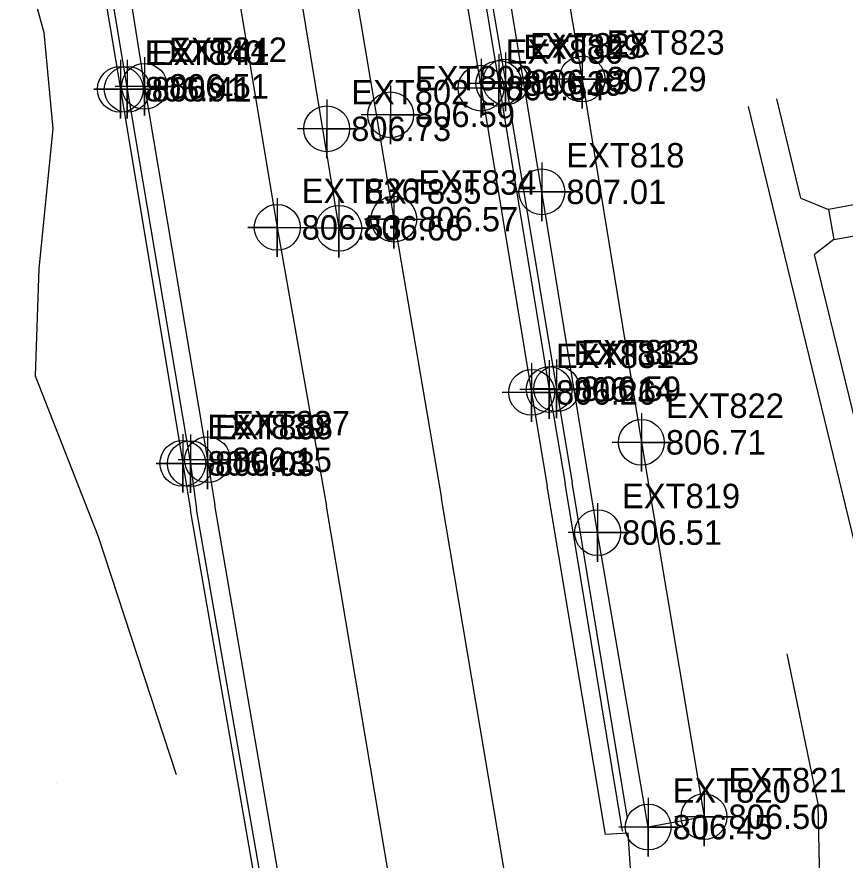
# Model space of a CAD drawing. Extents: x 1762120 to 1766775, y 709485 to 712965.
# Drawn here: x 1763815.9 to 1763900.7, y 712472.4 to 712558.7 of the extents above; entities that cross this region are included whole.
import ezdxf

# ---------------------------------------------------------------- set-up
doc = ezdxf.new("R2010")
doc.units = 0
for name, color, linetype in [('Exist DTM Crownline', 7, 'Continuous'), ('Exist DTM Crownline Cogo Elevation', 7, 'Continuous'), ('Exist DTM Crownline Cogo Number', 7, 'Continuous'), ('Exist DTM Crownline Cogo Point CELL', 7, 'Continuous'), ('Exist DTM Drainline', 7, 'Continuous'), ('Exist DTM Drainline Cogo Elevation', 7, 'Continuous'), ('Exist DTM Drainline Cogo Number', 7, 'Continuous'), ('Exist DTM Drainline Cogo Point CELL', 7, 'Continuous'), ('Exist DTM QL2 LIDAR Elevation Point', 7, 'Continuous'), ('Exist Roads Curbs', 7, 'Continuous'), ('Exist Roads Curbs Cogo Elevation', 7, 'Continuous'), ('Exist Roads Curbs Cogo Number', 7, 'Continuous'), ('Exist Roads Curbs Cogo Point CELL', 7, 'Continuous'), ('Exist Roads EOP', 7, 'Continuous'), ('Exist Roads EOP Cogo Elevation', 7, 'Continuous'), ('Exist Roads EOP Cogo Number', 7, 'Continuous'), ('Exist Roads EOP Cogo Point CELL', 7, 'Continuous'), ('Exist Roads EOP Other', 7, 'Continuous'), ('Exist Roads EOP Other Cogo Elevation', 7, 'Continuous'), ('Exist Roads EOP Other Cogo Number', 7, 'Continuous'), ('Exist Roads EOP Other Cogo Point CELL', 7, 'Continuous'), ('Exist Roads EOT', 7, 'Continuous'), ('Exist Roads EOT Cogo Elevation', 7, 'Continuous'), ('Exist Roads EOT Cogo Number', 7, 'Continuous'), ('Exist Roads EOT Cogo Point CELL', 7, 'Continuous'), ('Exist Utilities Sanitary Sewer UG Line Cogo Elevation', 7, 'Continuous'), ('Exist Utilities Sanitary Sewer UG Line Cogo Number', 7, 'Continuous'), ('Exist Utilities Sanitary Sewer UG Line Cogo Point CELL', 7, 'Continuous'), ('Exist Utilities Water UG Line SUE LOS C Cogo Elevation', 7, 'Continuous'), ('Exist Utilities Water UG Line SUE LOS C Cogo Number', 7, 'Continuous'), ('Exist Utilities Water UG Line SUE LOS C Cogo Point CELL', 7, 'Continuous'), ('PH Exist DTM Breakline', 7, 'Continuous')]:
    doc.layers.add(name, color=color, linetype=linetype)

msp = doc.modelspace()

# ---------------------------------------------------------------- linework, layer by layer
at = {"layer": 'Exist DTM Crownline'}
msp.add_line((1763843.626, 712568.925), (1763848.874, 712537.033), dxfattribs=at)
at = {"layer": 'Exist DTM Crownline Cogo Point CELL'}
msp.add_lwpolyline([(1763848.874, 712540.033), (1763848.874, 712534.033), (1763848.874, 712537.033), (1763851.874, 712537.033), (1763845.874, 712537.033)], dxfattribs=at)
msp.add_circle((1763848.874, 712537.033), 2.344, dxfattribs=at)
at = {"layer": 'Exist DTM Drainline'}
for p, q in [((1763877.892, 712475.314), (1763872.037, 712510.908)), ((1763841.037, 712469.687), (1763834.31, 712508.288))]:
    msp.add_line(p, q, dxfattribs=at)
for points in [[(1763824.048, 712570.37), (1763827.225, 712551.256), (1763833.688, 712512.933), (1763834.31, 712508.288)], [(1763862.254, 712569.784), (1763865.235, 712551.849), (1763870.388, 712520.524), (1763872.037, 712510.908)]]:
    msp.add_lwpolyline(points, dxfattribs=at)
at = {"layer": 'Exist DTM Drainline Cogo Point CELL'}
for points in [[(1763827.225, 712554.256), (1763827.225, 712548.256), (1763827.225, 712551.256), (1763830.225, 712551.256), (1763824.225, 712551.256)], [(1763865.235, 712554.849), (1763865.235, 712548.849), (1763865.235, 712551.849), (1763868.235, 712551.849), (1763862.235, 712551.849)], [(1763870.388, 712523.524), (1763870.388, 712517.524), (1763870.388, 712520.524), (1763873.388, 712520.524), (1763867.388, 712520.524)], [(1763833.688, 712515.933), (1763833.688, 712509.933), (1763833.688, 712512.933), (1763836.688, 712512.933), (1763830.688, 712512.933)]]:
    msp.add_lwpolyline(points, dxfattribs=at)
for centre in [(1763865.235, 712551.849), (1763827.225, 712551.256), (1763870.388, 712520.524), (1763833.688, 712512.933)]:
    msp.add_circle(centre, 2.344, dxfattribs=at)
at = {"layer": 'Exist DTM QL2 LIDAR Elevation Point'}
for p, q in [((1763900, 712550), (1763900, 712550)), ((1763819.96, 712480.153), (1763819.96, 712480.153))]:
    msp.add_line(p, q, dxfattribs=at)
at = {"layer": 'Exist Roads Curbs'}
for p, q in [((1763878.401, 712476.66), (1763872.734, 712511.007)), ((1763840.219, 712470.768), (1763833.683, 712508.175))]:
    msp.add_line(p, q, dxfattribs=at)
for points in [[(1763823.372, 712570.121), (1763826.523, 712551.26), (1763832.916, 712512.967), (1763833.683, 712508.175)], [(1763862.851, 712570.097), (1763865.927, 712552.006), (1763871.153, 712520.608), (1763872.734, 712511.007)]]:
    msp.add_lwpolyline(points, dxfattribs=at)
at = {"layer": 'Exist Roads Curbs Cogo Point CELL'}
for points in [[(1763865.927, 712555.006), (1763865.927, 712549.006), (1763865.927, 712552.006), (1763863.197, 712552.006), (1763868.927, 712552.006)], [(1763826.523, 712554.26), (1763826.523, 712548.26), (1763826.523, 712551.26), (1763823.793, 712551.26), (1763829.523, 712551.26)], [(1763871.153, 712523.608), (1763871.153, 712517.608), (1763871.153, 712520.608), (1763868.423, 712520.608), (1763874.153, 712520.608)], [(1763832.916, 712515.967), (1763832.916, 712509.967), (1763832.916, 712512.967), (1763830.186, 712512.967), (1763835.916, 712512.967)]]:
    msp.add_lwpolyline(points, dxfattribs=at)
for centre in [(1763865.927, 712552.006), (1763826.523, 712551.26), (1763871.153, 712520.608), (1763832.916, 712512.967)]:
    msp.add_circle(centre, 2.344, dxfattribs=at)
at = {"layer": 'Exist Roads EOP'}
for points in [[(1763825.965, 712570.729), (1763828.989, 712551.557), (1763835.435, 712513.335), (1763836.189, 712508.687)], [(1763860.431, 712569.332), (1763863.418, 712551.371), (1763868.592, 712520.228), (1763870.179, 712510.62)], [(1763884.183, 712443.669), (1763879.61, 712457.472), (1763878.458, 712475.13), (1763876.164, 712474.961), (1763870.179, 712510.62)], [(1763839.345, 712446.056), (1763842.4, 712453.309), (1763841.183, 712469.399), (1763842.828, 712470.046), (1763836.189, 712508.687)]]:
    msp.add_lwpolyline(points, dxfattribs=at)
at = {"layer": 'Exist Roads EOP Cogo Point CELL'}
for points in [[(1763828.989, 712554.557), (1763828.989, 712548.557), (1763828.989, 712551.557), (1763831.989, 712551.557), (1763825.989, 712551.557)], [(1763863.418, 712554.371), (1763863.418, 712548.371), (1763863.418, 712551.371), (1763866.418, 712551.371), (1763860.418, 712551.371)], [(1763868.592, 712523.228), (1763868.592, 712517.228), (1763868.592, 712520.228), (1763871.592, 712520.228), (1763865.592, 712520.228)], [(1763835.435, 712516.335), (1763835.435, 712510.335), (1763835.435, 712513.335), (1763838.435, 712513.335), (1763832.435, 712513.335)]]:
    msp.add_lwpolyline(points, dxfattribs=at)
for centre in [(1763828.989, 712551.557), (1763863.418, 712551.371), (1763868.592, 712520.228), (1763835.435, 712513.335)]:
    msp.add_circle(centre, 2.344, dxfattribs=at)
at = {"layer": 'Exist Roads EOP Other'}
msp.add_lwpolyline([(1763854.132, 712635.686), (1763859.673, 712642.69), (1763861.796, 712624.763), (1763862.778, 712618.431), (1763867.533, 712589.151), (1763873.757, 712552.303), (1763879.823, 712515.119), (1763886.226, 712476.795), (1763880.517, 712475.736), (1763875.337, 712505.878), (1763869.64, 712540.755), (1763863.568, 712577.565), (1763858.925, 712604.892)], close=True, dxfattribs=at)
at = {"layer": 'Exist Roads EOP Other Cogo Point CELL'}
for points in [[(1763873.757, 712555.303), (1763873.757, 712549.303), (1763873.757, 712552.303), (1763876.757, 712552.303), (1763870.757, 712552.303)], [(1763869.64, 712543.755), (1763869.64, 712537.755), (1763869.64, 712540.755), (1763872.64, 712540.755), (1763866.64, 712540.755)], [(1763879.823, 712518.119), (1763879.823, 712512.119), (1763879.823, 712515.119), (1763882.823, 712515.119), (1763876.823, 712515.119)], [(1763875.337, 712508.878), (1763875.337, 712502.878), (1763875.337, 712505.878), (1763878.337, 712505.878), (1763872.337, 712505.878)], [(1763886.226, 712479.795), (1763886.226, 712473.795), (1763886.226, 712476.795), (1763889.226, 712476.795), (1763883.226, 712476.795)], [(1763880.517, 712478.736), (1763880.517, 712472.736), (1763880.517, 712475.736), (1763883.517, 712475.736), (1763877.517, 712475.736)]]:
    msp.add_lwpolyline(points, dxfattribs=at)
for centre in [(1763873.757, 712552.303), (1763869.64, 712540.755), (1763879.823, 712515.119), (1763875.337, 712505.878), (1763886.226, 712476.795), (1763880.517, 712475.736)]:
    msp.add_circle(centre, 2.344, dxfattribs=at)
at = {"layer": 'Exist Roads EOT'}
for points in [[(1763849.139, 712569.759), (1763854.496, 712537.963), (1763859.372, 712509.363)], [(1763837.441, 712567.81), (1763842.568, 712537.12), (1763847.598, 712508.586)], [(1763870.661, 712442.063), (1763865.561, 712472.808), (1763859.372, 712509.363)], [(1763858.644, 712443.141), (1763854.01, 712470.555), (1763847.598, 712508.586)]]:
    msp.add_lwpolyline(points, dxfattribs=at)
at = {"layer": 'Exist Roads EOT Cogo Point CELL'}
for points in [[(1763854.496, 712540.963), (1763854.496, 712534.963), (1763854.496, 712537.963), (1763851.496, 712537.963), (1763857.496, 712537.963)], [(1763842.568, 712540.12), (1763842.568, 712534.12), (1763842.568, 712537.12), (1763839.568, 712537.12), (1763845.568, 712537.12)]]:
    msp.add_lwpolyline(points, dxfattribs=at)
for centre in [(1763854.496, 712537.963), (1763842.568, 712537.12)]:
    msp.add_circle(centre, 2.344, dxfattribs=at)
at = {"layer": 'Exist Utilities Sanitary Sewer UG Line Cogo Point CELL'}
msp.add_lwpolyline([(1763854.167, 712551.643), (1763854.167, 712545.643), (1763854.167, 712548.643), (1763857.167, 712548.643), (1763851.167, 712548.643)], dxfattribs=at)
msp.add_circle((1763854.167, 712548.643), 2.344, dxfattribs=at)
at = {"layer": 'Exist Utilities Water UG Line SUE LOS C Cogo Point CELL'}
msp.add_lwpolyline([(1763847.633, 712550.215), (1763847.633, 712544.215), (1763847.633, 712547.215), (1763850.633, 712547.215), (1763844.633, 712547.215)], dxfattribs=at)
msp.add_circle((1763847.633, 712547.215), 2.344, dxfattribs=at)
at = {"layer": 'PH Exist DTM Breakline'}
for p, q in [((1763896.143, 712540.128), (1763893.68, 712550.269)), ((1763902.567, 712500.966), (1763890.781, 712549.497)), ((1763896.143, 712540.128), (1763898.962, 712538.961)), ((1763899.523, 712535.884), (1763897.544, 712534.36)), ((1763903.063, 712511.632), (1763897.544, 712534.36))]:
    msp.add_line(p, q, dxfattribs=at)
for points in [[(1763815.936, 712567.159), (1763818.702, 712557.056), (1763819.598, 712547.204), (1763818.168, 712532.899), (1763817.792, 712521.914), (1763824.247, 712505.477), (1763832.242, 712481.102)], [(1763902.256, 712539.562), (1763898.962, 712538.961), (1763899.523, 712535.884), (1763902.777, 712536.478)], [(1763894.689, 712493.482), (1763897.873, 712478.115), (1763898.035, 712470.24)]]:
    msp.add_lwpolyline(points, dxfattribs=at)

# ---------------------------------------------------------------- texts
at = {"layer": 'Exist DTM Crownline Cogo Elevation'}
msp.add_text('806.66', height=2.5, dxfattribs=at).set_placement((1763851.374, 712535.783))
at = {"layer": 'Exist DTM Crownline Cogo Number'}
msp.add_text('EXT835', height=2.5, dxfattribs=at).set_placement((1763851.374, 712539.533))
at = {"layer": 'Exist DTM Drainline Cogo Elevation'}
for s, p in [('806.41', (1763829.725, 712550.006)), ('806.39', (1763867.735, 712550.599)), ('806.14', (1763872.888, 712519.274)), ('806.03', (1763836.188, 712511.683))]:
    msp.add_text(s, height=2.5, dxfattribs=at).set_placement(p)
at = {"layer": 'Exist DTM Drainline Cogo Number'}
for s, p in [('EXT829', (1763867.735, 712554.349)), ('EXT841', (1763829.725, 712553.756)), ('EXT832', (1763872.888, 712523.024)), ('EXT838', (1763836.188, 712515.433))]:
    msp.add_text(s, height=2.5, dxfattribs=at).set_placement(p)
at = {"layer": 'Exist Roads Curbs Cogo Elevation'}
for s, p in [('806.83', (1763868.427, 712550.756)), ('806.91', (1763829.023, 712550.01)), ('806.59', (1763873.653, 712519.358)), ('806.48', (1763835.416, 712511.717))]:
    msp.add_text(s, height=2.5, dxfattribs=at).set_placement(p)
at = {"layer": 'Exist Roads Curbs Cogo Number'}
for s, p in [('EXT828', (1763868.427, 712554.506)), ('EXT840', (1763829.023, 712553.76)), ('EXT833', (1763873.653, 712523.108)), ('EXT839', (1763835.416, 712515.467))]:
    msp.add_text(s, height=2.5, dxfattribs=at).set_placement(p)
at = {"layer": 'Exist Roads EOP Cogo Elevation'}
for s, p in [('806.51', (1763831.489, 712550.307)), ('806.54', (1763865.918, 712550.121)), ('806.26', (1763871.092, 712518.978)), ('806.15', (1763837.935, 712512.085))]:
    msp.add_text(s, height=2.5, dxfattribs=at).set_placement(p)
at = {"layer": 'Exist Roads EOP Cogo Number'}
for s, p in [('EXT842', (1763831.489, 712554.057)), ('EXT830', (1763865.918, 712553.871)), ('EXT831', (1763871.092, 712522.728)), ('EXT837', (1763837.935, 712515.835))]:
    msp.add_text(s, height=2.5, dxfattribs=at).set_placement(p)
at = {"layer": 'Exist Roads EOP Other Cogo Elevation'}
for s, p in [('807.29', (1763876.257, 712551.053)), ('807.01', (1763872.14, 712539.505)), ('806.71', (1763882.323, 712513.869)), ('806.51', (1763877.837, 712504.628)), ('806.50', (1763888.726, 712475.545)), ('806.45', (1763883.017, 712474.486))]:
    msp.add_text(s, height=2.5, dxfattribs=at).set_placement(p)
at = {"layer": 'Exist Roads EOP Other Cogo Number'}
for s, p in [('EXT823', (1763876.257, 712554.803)), ('EXT818', (1763872.14, 712543.255)), ('EXT822', (1763882.323, 712517.619)), ('EXT819', (1763877.837, 712508.378)), ('EXT821', (1763888.726, 712479.295)), ('EXT820', (1763883.017, 712478.236))]:
    msp.add_text(s, height=2.5, dxfattribs=at).set_placement(p)
at = {"layer": 'Exist Roads EOT Cogo Elevation'}
for s, p in [('806.57', (1763856.996, 712536.713)), ('806.53', (1763845.068, 712535.87))]:
    msp.add_text(s, height=2.5, dxfattribs=at).set_placement(p)
at = {"layer": 'Exist Roads EOT Cogo Number'}
for s, p in [('EXT834', (1763856.996, 712540.463)), ('EXT836', (1763845.068, 712539.62))]:
    msp.add_text(s, height=2.5, dxfattribs=at).set_placement(p)
at = {"layer": 'Exist Utilities Sanitary Sewer UG Line Cogo Elevation'}
msp.add_text('806.59', height=2.5, dxfattribs=at).set_placement((1763856.667, 712547.393))
at = {"layer": 'Exist Utilities Sanitary Sewer UG Line Cogo Number'}
msp.add_text('EXT803', height=2.5, dxfattribs=at).set_placement((1763856.667, 712551.143))
at = {"layer": 'Exist Utilities Water UG Line SUE LOS C Cogo Elevation'}
msp.add_text('806.73', height=2.5, dxfattribs=at).set_placement((1763850.133, 712545.965))
at = {"layer": 'Exist Utilities Water UG Line SUE LOS C Cogo Number'}
msp.add_text('EXT802', height=2.5, dxfattribs=at).set_placement((1763850.133, 712549.715))

doc.saveas('drawing.dxf')
